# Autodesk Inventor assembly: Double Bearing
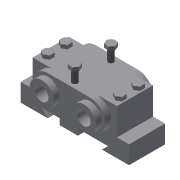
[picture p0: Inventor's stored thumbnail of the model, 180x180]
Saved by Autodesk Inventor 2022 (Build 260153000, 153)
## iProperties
Created: 2002-02
Part Number: Double Bearing
Document SubType Name: Assembly
Designer: ***
Control State: 0
Master: False
Checked Out: False
Shininess: 64.0
Length Units: 11269
Angle Units: 11279
Time Units: 11290
Mass Units: 11283
Length Display Precision: 3
Angle Display Precision: 2
Density: 0.0
Volumn: 0.0
Area: 0.0
PropertySet Name: Model Information
Author: ***
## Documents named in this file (5)
- D:\PROJECTS_2021\Resources\Tutorial Files\c10_Inv_2022_tut\c10_tut03_inv\Double Bearing Assembly\Double Bearing.iam
- D:\PROJECTS_2021\Resources\Tutorial Files\c10_Inv_2022_tut\c10_tut03_inv\Double Bearing Assembly\Base.ipt
- D:\PROJECTS_2021\Resources\Tutorial Files\c10_Inv_2022_tut\c10_tut03_inv\Double Bearing Assembly\Cap.ipt
- D:\PROJECTS_2021\Resources\Tutorial Files\c10_Inv_2022_tut\c10_tut03_inv\Double Bearing Assembly\Bushing.ipt
- D:\PROJECTS_2021\Resources\Tutorial Files\c10_Inv_2022_tut\c10_tut03_inv\Double Bearing Assembly\Bolt.ipt
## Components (10 placed, 4 different names)
1. Base:1 — Insert:1, Insert:2
2. Cap:1 — Insert:1, Insert:2, Insert:3, Insert:4, Insert:5, Insert:6
3. Bushing:1 — Insert:3
4. Bushing:2 — Insert:4
5. Bolt:1 — Insert:5
6. Bolt:6
7. Bolt:7
8. Bolt:8
9. Bolt:5 — Insert:6
10. Bolt:9
## Component patterns: Component Pattern 1 (4 elements), Component Pattern 2 (2 elements)
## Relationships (6: Insert 6)
- Insert:1: Base:1 ↔ Cap:1
- Insert:2: Base:1 ↔ Cap:1
- Insert:3: Cap:1 ↔ Bushing:1
- Insert:4: Cap:1 ↔ Bushing:2
- Insert:5: Cap:1 ↔ Bolt:1
- Insert:6: Cap:1 ↔ Bolt:5
